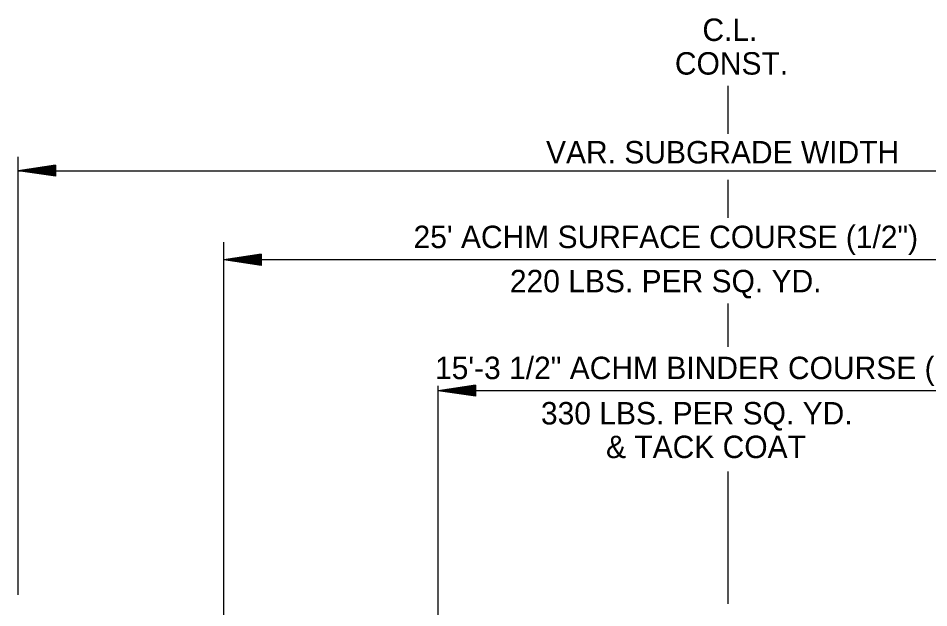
# Model space of a CAD drawing. Extents: x 1955768 to 1955917, y 566446 to 566546.
# Drawn here: x 1955820.67 to 1955845.04, y 566471.36 to 566487.13 of the extents above; entities that cross this region are included whole.
import ezdxf

# ---------------------------------------------------------------- set-up
doc = ezdxf.new("R2010")
doc.units = 0
doc.layers.add('R_Border', color=7, linetype='Continuous')
doc.layers.add('R_Grid', color=7, linetype='Continuous')

msp = doc.modelspace()

# ---------------------------------------------------------------- linework, layer by layer
at = {"layer": 'R_Grid'}
for p, q in [((1955839.673, 566484.038), (1955839.673, 566485.327)), ((1955820.673, 566471.713), (1955820.673, 566483.424)), ((1955821.673, 566483.204), (1955820.673, 566483.054)), ((1955820.673, 566483.054), (1955856.673, 566483.054)), ((1955821.673, 566482.904), (1955820.673, 566483.054)), ((1955821.673, 566483.179), (1955820.84, 566483.054)), ((1955821.673, 566482.929), (1955820.84, 566483.054)), ((1955821.673, 566483.153), (1955821.012, 566483.054)), ((1955821.673, 566482.954), (1955821.012, 566483.054)), ((1955821.673, 566483.128), (1955821.178, 566483.054)), ((1955821.673, 566482.979), (1955821.178, 566483.054)), ((1955821.673, 566483.102), (1955821.348, 566483.054)), ((1955821.673, 566483.005), (1955821.348, 566483.054)), ((1955821.673, 566483.077), (1955821.515, 566483.054)), ((1955821.673, 566483.03), (1955821.515, 566483.054)), ((1955821.673, 566483.204), (1955821.673, 566482.904)), ((1955839.673, 566481.79), (1955839.673, 566482.814)), ((1955826.173, 566476.637), (1955826.173, 566481.147)), ((1955827.173, 566480.819), (1955826.173, 566480.669)), ((1955851.173, 566480.669), (1955826.173, 566480.669)), ((1955827.173, 566480.519), (1955826.173, 566480.669)), ((1955827.173, 566480.794), (1955826.34, 566480.669)), ((1955827.173, 566480.544), (1955826.34, 566480.669)), ((1955827.173, 566480.768), (1955826.512, 566480.669)), ((1955827.173, 566480.569), (1955826.512, 566480.669)), ((1955827.173, 566480.743), (1955826.678, 566480.669)), ((1955827.173, 566480.594), (1955826.678, 566480.669)), ((1955827.173, 566480.717), (1955826.848, 566480.669)), ((1955827.173, 566480.62), (1955826.848, 566480.669)), ((1955827.173, 566480.692), (1955827.015, 566480.669)), ((1955827.173, 566480.645), (1955827.015, 566480.669)), ((1955827.173, 566480.819), (1955827.173, 566480.519)), ((1955839.673, 566478.34), (1955839.673, 566479.506)), ((1955832.912, 566477.319), (1955831.912, 566477.169)), ((1955831.912, 566470.669), (1955831.912, 566477.299)), ((1955832.912, 566477.294), (1955832.079, 566477.169)), ((1955832.912, 566477.268), (1955832.251, 566477.169)), ((1955832.912, 566477.243), (1955832.418, 566477.169)), ((1955832.912, 566477.217), (1955832.587, 566477.169)), ((1955832.912, 566477.192), (1955832.754, 566477.169)), ((1955832.912, 566477.319), (1955832.912, 566477.019)), ((1955847.423, 566477.169), (1955831.912, 566477.169)), ((1955832.912, 566477.019), (1955831.912, 566477.169)), ((1955832.912, 566477.044), (1955832.079, 566477.169)), ((1955832.912, 566477.069), (1955832.251, 566477.169)), ((1955832.912, 566477.094), (1955832.418, 566477.169)), ((1955832.912, 566477.12), (1955832.587, 566477.169)), ((1955832.912, 566477.145), (1955832.754, 566477.169)), ((1955826.173, 566469.009), (1955826.173, 566476.637)), ((1955839.673, 566471.47), (1955839.673, 566475.007))]:
    msp.add_line(p, q, dxfattribs=at)

# ---------------------------------------------------------------- texts
at = {"layer": 'R_Border'}
for s, p in [('C.L.', (1955838.981, 566486.525)), ('CONST.', (1955838.244, 566485.625)), ('VAR. SUBGRADE WIDTH', (1955834.796, 566483.249)), ('25\' ACHM SURFACE COURSE (1/2")', (1955831.251, 566480.984)), ('220 LBS. PER SQ. YD.', (1955833.829, 566479.802)), ('15\'-3 1/2" ACHM BINDER COURSE (1")', (1955831.825, 566477.479)), ('330 LBS. PER SQ. YD. ', (1955834.66, 566476.267)), ('& TACK COAT', (1955836.401, 566475.367))]:
    msp.add_text(s, height=0.6, dxfattribs=at).set_placement(p)

doc.saveas('drawing.dxf')
